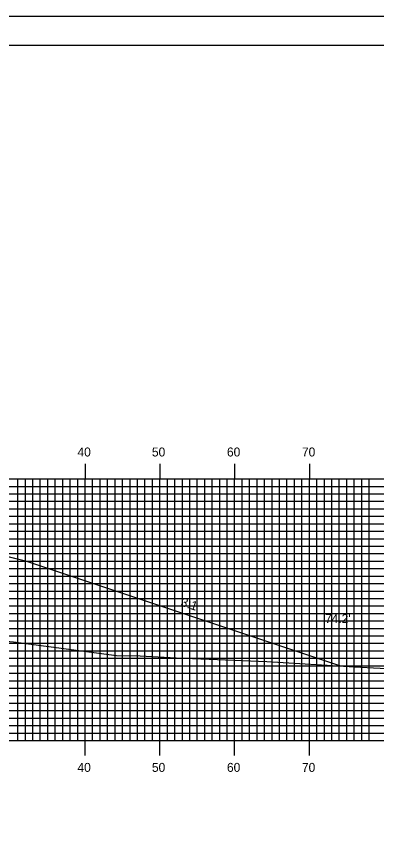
# Model space of a CAD drawing. Extents: x 1815702 to 1816046, y 442591 to 442811.
# Drawn here: x 1815898.9 to 1815947, y 442700.5 to 442810.5 of the extents above; entities that cross this region are included whole.
import ezdxf

# ---------------------------------------------------------------- set-up
doc = ezdxf.new("R2010")
doc.units = 0
for name, color, linetype in [('ANNOTATION', 7, 'Continuous'), ('BORDER', 7, 'Continuous'), ('D_Roadway_Centerline', 7, 'Continuous'), ('D_Roadway_SlopeLines', 7, 'Continuous'), ('D_Text_Standard', 7, 'Continuous'), ('H_V ANNOTATION', 7, 'Continuous'), ('MAJOR', 7, 'Continuous'), ('MINOR', 7, 'Continuous'), ('PLOT BOUNDARY', 7, 'Continuous'), ('S_Roadway_Centerline', 7, 'Continuous')]:
    doc.layers.add(name, color=color, linetype=linetype)

msp = doc.modelspace()

# ---------------------------------------------------------------- linework, layer by layer
at = {"layer": 'BORDER'}
msp.add_lwpolyline([(1815718.45, 442596.67), (1816038.45, 442596.67), (1816038.45, 442806.67), (1815718.45, 442806.67)], close=True, dxfattribs=at)
at = {"layer": 'D_Roadway_Centerline'}
msp.add_lwpolyline([(1815820.65, 442733.86), (1815836.05, 442737.71), (1815837.87, 442738.17), (1815848.05, 442740.71), (1815856.05, 442741.03), (1815868.05, 442741.27), (1815880.05, 442741.03), (1815888.05, 442740.71), (1815898.22, 442738.17), (1815900.05, 442737.71), (1815942.23, 442723.65)], dxfattribs=at)
at = {"layer": 'D_Roadway_SlopeLines'}
msp.add_lwpolyline([(1815888.05, 442740.71), (1815900.05, 442737.71), (1815942.23, 442723.65)], dxfattribs=at)
at = {"layer": 'MAJOR'}
for p, q in [((1815908.05, 442750.67), (1815908.05, 442748.67)), ((1815918.05, 442750.67), (1815918.05, 442748.67)), ((1815928.05, 442750.67), (1815928.05, 442748.67)), ((1815938.05, 442750.67), (1815938.05, 442748.67)), ((1815728.05, 442748.67), (1816008.05, 442748.67)), ((1815728.05, 442748.67), (1816008.05, 442748.67)), ((1815908.05, 442713.67), (1815908.05, 442748.67)), ((1815918.05, 442713.67), (1815918.05, 442748.67)), ((1815928.05, 442713.67), (1815928.05, 442748.67)), ((1815938.05, 442713.67), (1815938.05, 442748.67)), ((1815728.05, 442743.67), (1816008.05, 442743.67)), ((1815728.05, 442738.67), (1816008.05, 442738.67)), ((1815728.05, 442733.67), (1816008.05, 442733.67)), ((1815728.05, 442728.67), (1816008.05, 442728.67)), ((1815728.05, 442723.67), (1816008.05, 442723.67)), ((1815728.05, 442718.67), (1816008.05, 442718.67)), ((1815728.05, 442713.67), (1816008.05, 442713.67)), ((1815728.05, 442713.67), (1816008.05, 442713.67)), ((1815908.05, 442711.66), (1815908.05, 442713.67)), ((1815918.05, 442711.66), (1815918.05, 442713.67)), ((1815928.05, 442711.66), (1815928.05, 442713.67)), ((1815938.05, 442711.66), (1815938.05, 442713.67))]:
    msp.add_line(p, q, dxfattribs=at)
at = {"layer": 'MINOR'}
for p, q in [((1815899.05, 442713.67), (1815899.05, 442748.67)), ((1815900.05, 442713.67), (1815900.05, 442748.67)), ((1815901.05, 442713.67), (1815901.05, 442748.67)), ((1815902.05, 442713.67), (1815902.05, 442748.67)), ((1815903.05, 442713.67), (1815903.05, 442748.67)), ((1815904.05, 442713.67), (1815904.05, 442748.67)), ((1815905.05, 442713.67), (1815905.05, 442748.67)), ((1815906.05, 442713.67), (1815906.05, 442748.67)), ((1815907.05, 442713.67), (1815907.05, 442748.67)), ((1815909.05, 442713.67), (1815909.05, 442748.67)), ((1815910.05, 442713.67), (1815910.05, 442748.67)), ((1815911.05, 442713.67), (1815911.05, 442748.67)), ((1815912.05, 442713.67), (1815912.05, 442748.67)), ((1815913.05, 442713.67), (1815913.05, 442748.67)), ((1815914.05, 442713.67), (1815914.05, 442748.67)), ((1815915.05, 442713.67), (1815915.05, 442748.67)), ((1815916.05, 442713.67), (1815916.05, 442748.67)), ((1815917.05, 442713.67), (1815917.05, 442748.67)), ((1815919.05, 442713.67), (1815919.05, 442748.67)), ((1815920.05, 442713.67), (1815920.05, 442748.67)), ((1815921.05, 442713.67), (1815921.05, 442748.67)), ((1815922.05, 442713.67), (1815922.05, 442748.67)), ((1815923.05, 442713.67), (1815923.05, 442748.67)), ((1815924.05, 442713.67), (1815924.05, 442748.67)), ((1815925.05, 442713.67), (1815925.05, 442748.67)), ((1815926.05, 442713.67), (1815926.05, 442748.67)), ((1815927.05, 442713.67), (1815927.05, 442748.67)), ((1815929.05, 442713.67), (1815929.05, 442748.67)), ((1815930.05, 442713.67), (1815930.05, 442748.67)), ((1815931.05, 442713.67), (1815931.05, 442748.67)), ((1815932.05, 442713.67), (1815932.05, 442748.67)), ((1815933.05, 442713.67), (1815933.05, 442748.67)), ((1815934.05, 442713.67), (1815934.05, 442748.67)), ((1815935.05, 442713.67), (1815935.05, 442748.67)), ((1815936.05, 442713.67), (1815936.05, 442748.67)), ((1815937.05, 442713.67), (1815937.05, 442748.67)), ((1815939.05, 442713.67), (1815939.05, 442748.67)), ((1815940.05, 442713.67), (1815940.05, 442748.67)), ((1815941.05, 442713.67), (1815941.05, 442748.67)), ((1815942.05, 442713.67), (1815942.05, 442748.67)), ((1815943.05, 442713.67), (1815943.05, 442748.67)), ((1815944.05, 442713.67), (1815944.05, 442748.67)), ((1815945.05, 442713.67), (1815945.05, 442748.67)), ((1815946.05, 442713.67), (1815946.05, 442748.67)), ((1815728.05, 442747.67), (1816008.05, 442747.67)), ((1815728.05, 442746.67), (1816008.05, 442746.67)), ((1815728.05, 442745.67), (1816008.05, 442745.67)), ((1815728.05, 442744.67), (1816008.05, 442744.67)), ((1815728.05, 442742.67), (1816008.05, 442742.67)), ((1815728.05, 442741.67), (1816008.05, 442741.67)), ((1815728.05, 442740.67), (1816008.05, 442740.67)), ((1815728.05, 442739.67), (1816008.05, 442739.67)), ((1815728.05, 442737.67), (1816008.05, 442737.67)), ((1815728.05, 442736.67), (1816008.05, 442736.67)), ((1815728.05, 442735.67), (1816008.05, 442735.67)), ((1815728.05, 442734.67), (1816008.05, 442734.67)), ((1815728.05, 442732.67), (1816008.05, 442732.67)), ((1815728.05, 442731.67), (1816008.05, 442731.67)), ((1815728.05, 442730.67), (1816008.05, 442730.67)), ((1815728.05, 442729.67), (1816008.05, 442729.67)), ((1815728.05, 442727.67), (1816008.05, 442727.67)), ((1815728.05, 442726.67), (1816008.05, 442726.67)), ((1815728.05, 442725.67), (1816008.05, 442725.67)), ((1815728.05, 442724.67), (1816008.05, 442724.67)), ((1815728.05, 442722.67), (1816008.05, 442722.67)), ((1815728.05, 442721.67), (1816008.05, 442721.67)), ((1815728.05, 442720.67), (1816008.05, 442720.67)), ((1815728.05, 442719.67), (1816008.05, 442719.67)), ((1815728.05, 442717.67), (1816008.05, 442717.67)), ((1815728.05, 442716.67), (1816008.05, 442716.67)), ((1815728.05, 442715.67), (1816008.05, 442715.67)), ((1815728.05, 442714.67), (1816008.05, 442714.67))]:
    msp.add_line(p, q, dxfattribs=at)
at = {"layer": 'PLOT BOUNDARY'}
msp.add_lwpolyline([(1815702.26, 442590.55), (1816042.26, 442590.55), (1816042.26, 442810.55), (1815702.26, 442810.55)], close=True, dxfattribs=at)
at = {"layer": 'S_Roadway_Centerline'}
msp.add_lwpolyline([(1815813.52, 442734.44), (1815817.67, 442734.08), (1815831.05, 442733.07), (1815831.86, 442733.02), (1815834.91, 442732.5), (1815845.17, 442730.68), (1815847.19, 442730.5), (1815858.01, 442729.87), (1815863.98, 442729.58), (1815871.95, 442729.26), (1815881.08, 442728.48), (1815884.61, 442728.07), (1815898.48, 442726.85), (1815912.25, 442725.06), (1815915.4, 442724.99), (1815920.24, 442724.75), (1815932.35, 442724.25), (1815944.06, 442723.54), (1815950.07, 442723.22)], dxfattribs=at)

# ---------------------------------------------------------------- texts
at = {"layer": 'ANNOTATION'}
msp.add_text('3:1', height=1.2, rotation=341.5652, dxfattribs=at).set_placement((1815920.74, 442731.72))
at = {"layer": 'D_Text_Standard'}
msp.add_text("74.2'", height=1.2, dxfattribs=at).set_placement((1815940.13, 442729.37))
at = {"layer": 'H_V ANNOTATION'}
for s, p in [('40', (1815907.02, 442751.67)), ('50', (1815916.98, 442751.67)), ('60', (1815927.02, 442751.67)), ('70', (1815937.05, 442751.67)), ('40', (1815907.02, 442709.47)), ('50', (1815916.98, 442709.47)), ('60', (1815927.02, 442709.47)), ('70', (1815937.05, 442709.47))]:
    msp.add_text(s, height=1.2, dxfattribs=at).set_placement(p)

doc.saveas('drawing.dxf')
